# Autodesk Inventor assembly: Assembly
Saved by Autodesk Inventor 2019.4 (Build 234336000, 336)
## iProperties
Created: 2020-04
Part Number: Assembly
Document SubType Name: Assembly
Designer: Administrator
Title: Assembly v159
Author: Administrator
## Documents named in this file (40)
- c:\worker\convert-fusion-r03\tmp\job-1\48\output\files\ccae6ef3-9f0e-42ff-b199-3a2c6474057a\3e9963f0-b3bd-4149-84e4-45ce88d6f4f1.iam
- c:\worker\convert-fusion-r03\tmp\job-1\48\output\files\ccae6ef3-9f0e-42ff-b199-3a2c6474057a\4mmBearing v4.iam
- c:\worker\convert-fusion-r03\tmp\job-1\48\output\files\ccae6ef3-9f0e-42ff-b199-3a2c6474057a\MainShaft.ipt
- c:\worker\convert-fusion-r03\tmp\job-1\48\output\files\ccae6ef3-9f0e-42ff-b199-3a2c6474057a\4mmBearing v4_1.iam
- c:\worker\convert-fusion-r03\tmp\job-1\48\output\files\ccae6ef3-9f0e-42ff-b199-3a2c6474057a\6mmBearing v2.ipt
- c:\worker\convert-fusion-r03\tmp\job-1\48\output\files\ccae6ef3-9f0e-42ff-b199-3a2c6474057a\BrassTube v3.ipt
- c:\worker\convert-fusion-r03\tmp\job-1\48\output\files\ccae6ef3-9f0e-42ff-b199-3a2c6474057a\Spacer v9.ipt
- c:\worker\convert-fusion-r03\tmp\job-1\48\output\files\ccae6ef3-9f0e-42ff-b199-3a2c6474057a\Generator_Gear_large(21 teeth) v5.ipt
- c:\worker\convert-fusion-r03\tmp\job-1\48\output\files\ccae6ef3-9f0e-42ff-b199-3a2c6474057a\Generator v12.iam
- c:\worker\convert-fusion-r03\tmp\job-1\48\output\files\ccae6ef3-9f0e-42ff-b199-3a2c6474057a\Generator_gear_small(10 teeth) v3.ipt
- c:\worker\convert-fusion-r03\tmp\job-1\48\output\files\ccae6ef3-9f0e-42ff-b199-3a2c6474057a\Servo v14.ipt
- c:\worker\convert-fusion-r03\tmp\job-1\48\output\files\ccae6ef3-9f0e-42ff-b199-3a2c6474057a\Rotor_mount v9.ipt
- c:\worker\convert-fusion-r03\tmp\job-1\48\output\files\ccae6ef3-9f0e-42ff-b199-3a2c6474057a\Blade_mount v18.iam
- c:\worker\convert-fusion-r03\tmp\job-1\48\output\files\ccae6ef3-9f0e-42ff-b199-3a2c6474057a\Blade_mount v18_1.iam
- c:\worker\convert-fusion-r03\tmp\job-1\48\output\files\ccae6ef3-9f0e-42ff-b199-3a2c6474057a\Blade_mount v18_2.iam
- c:\worker\convert-fusion-r03\tmp\job-1\48\output\files\ccae6ef3-9f0e-42ff-b199-3a2c6474057a\Blade v3.ipt
- c:\worker\convert-fusion-r03\tmp\job-1\48\output\files\ccae6ef3-9f0e-42ff-b199-3a2c6474057a\BallJoint v14.iam
- c:\worker\convert-fusion-r03\tmp\job-1\48\output\files\ccae6ef3-9f0e-42ff-b199-3a2c6474057a\BallJoint v14_1.iam
- c:\worker\convert-fusion-r03\tmp\job-1\48\output\files\ccae6ef3-9f0e-42ff-b199-3a2c6474057a\BallJoint v14_2.iam
- c:\worker\convert-fusion-r03\tmp\job-1\48\output\files\ccae6ef3-9f0e-42ff-b199-3a2c6474057a\BallJoint v14_3.iam
- c:\worker\convert-fusion-r03\tmp\job-1\48\output\files\ccae6ef3-9f0e-42ff-b199-3a2c6474057a\BallJoint v14_4.iam
- c:\worker\convert-fusion-r03\tmp\job-1\48\output\files\ccae6ef3-9f0e-42ff-b199-3a2c6474057a\BallJoint v14_5.iam
- c:\worker\convert-fusion-r03\tmp\job-1\48\output\files\ccae6ef3-9f0e-42ff-b199-3a2c6474057a\Rotor_Bearing_mount v5.ipt
- c:\worker\convert-fusion-r03\tmp\job-1\48\output\files\ccae6ef3-9f0e-42ff-b199-3a2c6474057a\Blade_Shaft_Retention_Ring v1.ipt
- c:\worker\convert-fusion-r03\tmp\job-1\48\output\files\ccae6ef3-9f0e-42ff-b199-3a2c6474057a\3mmBearing v2.ipt
- c:\worker\convert-fusion-r03\tmp\job-1\48\output\files\ccae6ef3-9f0e-42ff-b199-3a2c6474057a\20mmRod v1.ipt
- c:\worker\convert-fusion-r03\tmp\job-1\48\output\files\ccae6ef3-9f0e-42ff-b199-3a2c6474057a\Swash_Plate_Stationary_Mount v3.ipt
- c:\worker\convert-fusion-r03\tmp\job-1\48\output\files\ccae6ef3-9f0e-42ff-b199-3a2c6474057a\BallJoint v14_6.iam
- c:\worker\convert-fusion-r03\tmp\job-1\48\output\files\ccae6ef3-9f0e-42ff-b199-3a2c6474057a\Servo_arm v5.ipt
- c:\worker\convert-fusion-r03\tmp\job-1\48\output\files\ccae6ef3-9f0e-42ff-b199-3a2c6474057a\Servo_Connector_Rod v1.ipt
- c:\worker\convert-fusion-r03\tmp\job-1\48\output\files\ccae6ef3-9f0e-42ff-b199-3a2c6474057a\Tower v1.ipt
- c:\worker\convert-fusion-r03\tmp\job-1\48\output\files\ccae6ef3-9f0e-42ff-b199-3a2c6474057a\NacelleFront.ipt
- c:\worker\convert-fusion-r03\tmp\job-1\48\output\files\ccae6ef3-9f0e-42ff-b199-3a2c6474057a\ServoMountPlate.ipt
- c:\worker\convert-fusion-r03\tmp\job-1\48\output\files\ccae6ef3-9f0e-42ff-b199-3a2c6474057a\NacelleRear.ipt
- c:\worker\convert-fusion-r03\tmp\job-1\48\output\files\ccae6ef3-9f0e-42ff-b199-3a2c6474057a\MotorMountPlate.ipt
- c:\worker\convert-fusion-r03\tmp\job-1\48\output\files\ccae6ef3-9f0e-42ff-b199-3a2c6474057a\MotorMount2.ipt
- c:\worker\convert-fusion-r03\tmp\job-1\48\output\files\ccae6ef3-9f0e-42ff-b199-3a2c6474057a\MotorMount1.ipt
- c:\worker\convert-fusion-r03\tmp\job-1\48\output\files\ccae6ef3-9f0e-42ff-b199-3a2c6474057a\BottomPlate.ipt
- c:\worker\convert-fusion-r03\tmp\job-1\48\output\files\ccae6ef3-9f0e-42ff-b199-3a2c6474057a\MountRing1.ipt
- c:\worker\convert-fusion-r03\tmp\job-1\48\output\files\ccae6ef3-9f0e-42ff-b199-3a2c6474057a\MountRing2.ipt
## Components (50 placed, 30 different names)
1. 4mmBearing v4:1 [sub-assembly]
2. MainShaft:1
3. 4mmBearing v4:2 [sub-assembly]
4. 6mmBearing v2:1
5. BrassTube v3:1
6. Spacer v9:1
7. Generator_Gear_large(21 teeth) v5:1
8. Generator v12:1 [sub-assembly]
9. Generator_gear_small(10 teeth) v3:1
10. Servo v14:1
11. Rotor_mount v9:1
12. Blade_mount v18:1 [sub-assembly]
13. Blade_mount v18:2 [sub-assembly]
14. Blade_mount v18:3 [sub-assembly]
15. Blade v3:1
16. Blade v3:2
17. Blade v3:3
18. BallJoint v14:1 [sub-assembly]
19. BallJoint v14:2 [sub-assembly]
20. BallJoint v14:3 [sub-assembly]
21. BallJoint v14:4 [sub-assembly]
22. BallJoint v14:5 [sub-assembly]
23. BallJoint v14:6 [sub-assembly]
24. Rotor_Bearing_mount v5:1
25. Rotor_Bearing_mount v5:2
26. Rotor_Bearing_mount v5:3
27. Blade_Shaft_Retention_Ring v1:1
28. Blade_Shaft_Retention_Ring v1:2
29. Blade_Shaft_Retention_Ring v1:3
30. 3mmBearing v2:3
31. 3mmBearing v2:4
32. 3mmBearing v2:5
33. 20mmRod v1:5
34. 20mmRod v1:6
35. 20mmRod v1:7
36. Swash_Plate_Stationary_Mount v3:1
37. BallJoint v14:7 [sub-assembly]
38. Servo_arm v5:1
39. Servo_Connector_Rod v1:1
40. Tower v1:1
41. Tower v1:2
42. NacelleFront:1
43. ServoMountPlate:1
44. NacelleRear:1
45. MotorMountPlate:1
46. MotorMount2:1
47. MotorMount1:1
48. BottomPlate:1
49. MountRing1:1
50. MountRing2:1
